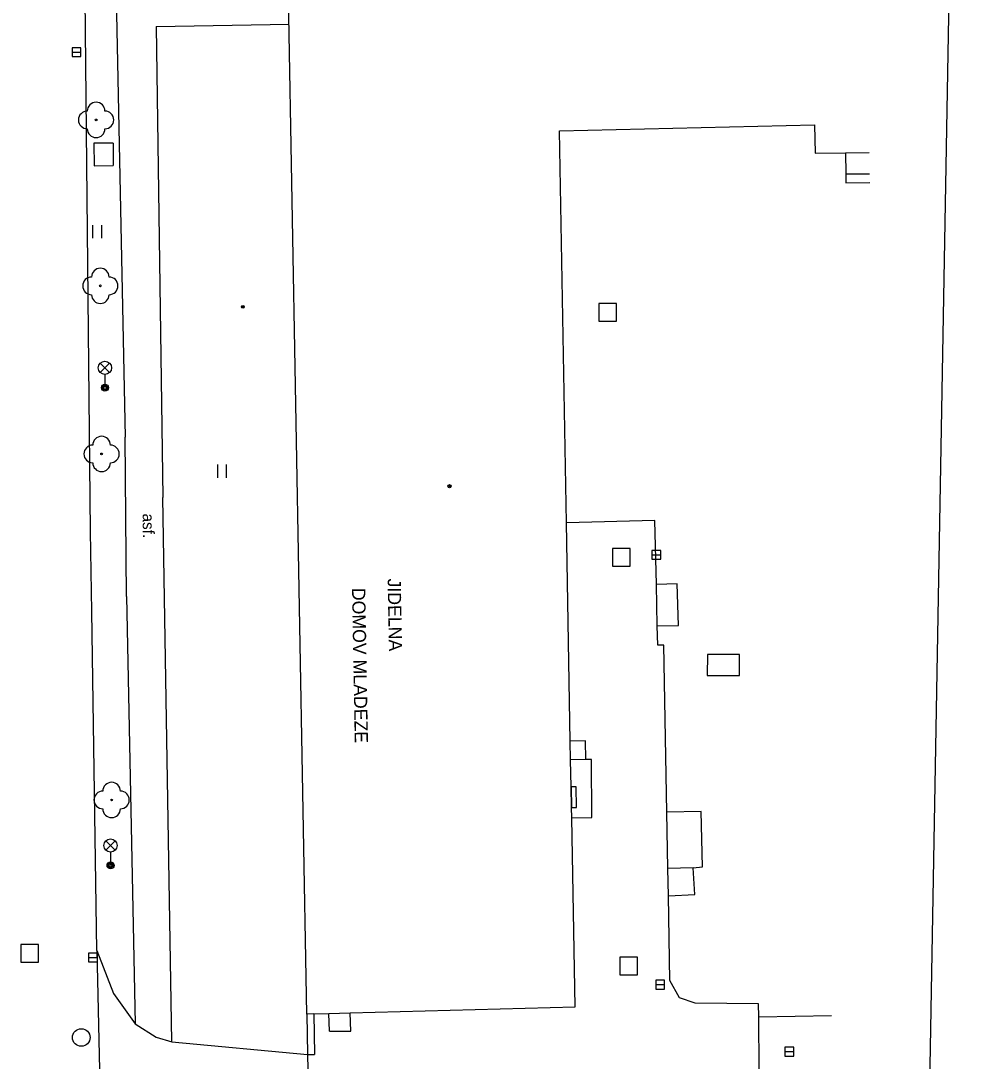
# Model space of a CAD drawing. Extents: x -641829 to -641525, y -1114855 to -1114359.
# Drawn here: x -641579.2 to -641525.3, y -1114496 to -1114437 of the extents above; entities that cross this region are included whole.
import ezdxf

# ---------------------------------------------------------------- set-up
doc = ezdxf.new("R2010")
doc.units = 0
for name, color, linetype in [('Vrstva 1', 7, 'Continuous'), ('Vrstva 10', 7, 'Continuous'), ('Vrstva 11', 7, 'Continuous'), ('Vrstva 20', 7, 'Continuous'), ('Vrstva 22', 7, 'Continuous'), ('Vrstva 24', 7, 'Continuous'), ('Vrstva 26', 7, 'Continuous'), ('Vrstva 27', 7, 'Continuous'), ('Vrstva 33', 7, 'Continuous'), ('Vrstva 36', 7, 'Continuous'), ('Vrstva 39', 7, 'Continuous'), ('Vrstva 40', 7, 'Continuous'), ('Vrstva 41', 7, 'Continuous'), ('Vrstva 5', 7, 'Continuous'), ('Vrstva 7', 7, 'Continuous'), ('Vrstva 8', 7, 'Continuous')]:
    doc.layers.add(name, color=color, linetype=linetype)

msp = doc.modelspace()

# ---------------------------------------------------------------- linework, layer by layer
at = {"layer": 'Vrstva 1'}
msp.add_line((-641533.66, -1114832.21), (-641525.3, -1114362.64), dxfattribs=at)
at = {"layer": 'Vrstva 10'}
for p, q in [((-641575.3, -1114465.98), (-641575.62, -1114434.15)), ((-641543.3, -1114465.35), (-641548.31, -1114465.48)), ((-641543.21, -1114468.98), (-641543.3, -1114465.35)), ((-641575.23, -1114470.51), (-641575.3, -1114465.98)), ((-641543.16, -1114471.33), (-641543.21, -1114468.98)), ((-641574.94, -1114489.73), (-641575.23, -1114470.51)), ((-641543.13, -1114472.43), (-641543.16, -1114471.33)), ((-641542.79, -1114472.42), (-641543.13, -1114472.43)), ((-641542.62, -1114481.89), (-641542.79, -1114472.42)), ((-641542.56, -1114485.08), (-641542.62, -1114481.89)), ((-641542.53, -1114486.64), (-641542.56, -1114485.08)), ((-641542.44, -1114491.44), (-641542.53, -1114486.64)), ((-641574.94, -1114489.73), (-641574.64, -1114503.41)), ((-641574.94, -1114489.73), (-641574, -1114492.18)), ((-641541.89, -1114492.42), (-641542.44, -1114491.44)), ((-641574, -1114492.18), (-641572.76, -1114493.9)), ((-641541.01, -1114492.72), (-641541.89, -1114492.42)), ((-641537.41, -1114492.76), (-641541.01, -1114492.72)), ((-641537.39, -1114493.5), (-641537.41, -1114492.76)), ((-641537.38, -1114496.49), (-641537.39, -1114493.5)), ((-641572.76, -1114493.9), (-641571.57, -1114494.65)), ((-641571.57, -1114494.65), (-641570.68, -1114494.91)), ((-641570.68, -1114494.91), (-641562.99, -1114495.64))]:
    msp.add_line(p, q, dxfattribs=at)
at = {"layer": 'Vrstva 11'}
for p, q in [((-641573.9, -1114433.06), (-641573.34, -1114460.63)), ((-641571.58, -1114437.35), (-641564.04, -1114437.21)), ((-641571.58, -1114437.35), (-641571.19, -1114464.05)), ((-641575.11, -1114443.96), (-641575.09, -1114445.24)), ((-641574.02, -1114443.96), (-641575.11, -1114443.96)), ((-641574.02, -1114443.96), (-641574.02, -1114445.22)), ((-641532.49, -1114444.5), (-641532.47, -1114445.7)), ((-641575.09, -1114445.24), (-641574.02, -1114445.22)), ((-641532.47, -1114445.7), (-641531.12, -1114445.69)), ((-641532.47, -1114445.7), (-641532.47, -1114446.2)), ((-641532.47, -1114446.2), (-641531.11, -1114446.19)), ((-641573.26, -1114469.66), (-641573.34, -1114460.63)), ((-641570.68, -1114494.91), (-641571.19, -1114464.05)), ((-641542.03, -1114468.95), (-641543.21, -1114468.98)), ((-641541.95, -1114471.3), (-641542.03, -1114468.95)), ((-641573.26, -1114469.66), (-641572.76, -1114493.9)), ((-641543.16, -1114471.33), (-641541.95, -1114471.3)), ((-641540.31, -1114472.95), (-641540.32, -1114474.14)), ((-641538.49, -1114472.96), (-641540.31, -1114472.95)), ((-641538.5, -1114474.15), (-641538.49, -1114472.96)), ((-641540.32, -1114474.14), (-641538.5, -1114474.15)), ((-641547.23, -1114477.85), (-641548.09, -1114477.87)), ((-641547.21, -1114478.91), (-641547.23, -1114477.85)), ((-641546.88, -1114478.9), (-641547.21, -1114478.91)), ((-641546.87, -1114482.19), (-641546.88, -1114478.9)), ((-641547.21, -1114478.91), (-641548.07, -1114478.92)), ((-641540.66, -1114481.85), (-641542.62, -1114481.89)), ((-641540.59, -1114484.99), (-641540.66, -1114481.85)), ((-641548.01, -1114482.21), (-641546.87, -1114482.19)), ((-641541.12, -1114485.05), (-641542.56, -1114485.08)), ((-641541.12, -1114485.05), (-641540.59, -1114484.99)), ((-641541.02, -1114486.56), (-641541.12, -1114485.05)), ((-641542.53, -1114486.64), (-641541.02, -1114486.56)), ((-641561.75, -1114494.31), (-641561.78, -1114493.31)), ((-641560.54, -1114494.31), (-641560.57, -1114493.27)), ((-641537.39, -1114493.5), (-641533.28, -1114493.43)), ((-641561.75, -1114494.31), (-641560.54, -1114494.31))]:
    msp.add_line(p, q, dxfattribs=at)
at = {"layer": 'Vrstva 20'}
for radius in [0.075, 0.0204]:
    msp.add_circle((-641566.66, -1114453.24), radius, dxfattribs=at)
at = {"layer": 'Vrstva 22'}
for centre in [(-641574.98, -1114442.64), (-641574.74, -1114452.05), (-641574.67, -1114461.58), (-641574.1, -1114481.2)]:
    msp.add_circle(centre, 0.05, dxfattribs=at)
for centre, start, end in [((-641574.98, -1114442.14), 0, 180), ((-641575.48, -1114442.64), 90, 270), ((-641574.48, -1114442.64), 270, 90), ((-641574.98, -1114443.14), 180, 0), ((-641574.74, -1114451.55), 0, 180), ((-641575.24, -1114452.05), 90, 270), ((-641574.24, -1114452.05), 270, 90), ((-641574.74, -1114452.55), 180, 0), ((-641574.67, -1114461.08), 0, 180), ((-641575.17, -1114461.58), 90, 270), ((-641574.17, -1114461.58), 270, 90), ((-641574.67, -1114462.08), 180, 0), ((-641574.1, -1114480.7), 0, 180), ((-641574.6, -1114481.2), 90, 270), ((-641573.6, -1114481.2), 270, 90), ((-641574.1, -1114481.7), 180, 0)]:
    msp.add_arc(centre, 0.5, start, end, dxfattribs=at)
at = {"layer": 'Vrstva 24'}
msp.add_lwpolyline([(-641547.74, -1114481.62), (-641547.76, -1114480.45), (-641548.04, -1114480.46), (-641548.02, -1114481.63), (-641547.74, -1114481.62)], dxfattribs=at)
at = {"layer": 'Vrstva 26'}
for points in [[(-641546.47, -1114454.05), (-641545.47, -1114454.05), (-641545.47, -1114453.05), (-641546.47, -1114453.05)], [(-641545.7, -1114467.94), (-641544.7, -1114467.94), (-641544.7, -1114466.94), (-641545.7, -1114466.94)], [(-641578.25, -1114489.39), (-641579.25, -1114489.39), (-641579.25, -1114490.39), (-641578.25, -1114490.39)], [(-641545.28, -1114491.11), (-641544.28, -1114491.11), (-641544.28, -1114490.11), (-641545.28, -1114490.11)]]:
    msp.add_lwpolyline(points, close=True, dxfattribs=at)
at = {"layer": 'Vrstva 27'}
for p, q in [((-641576.34, -1114438.8), (-641575.84, -1114438.8)), ((-641543.46, -1114467.3), (-641542.96, -1114467.3)), ((-641575.41, -1114490.13), (-641574.91, -1114490.13)), ((-641543.24, -1114491.67), (-641542.74, -1114491.67)), ((-641535.92, -1114495.47), (-641535.42, -1114495.47))]:
    msp.add_line(p, q, dxfattribs=at)
for points in [[(-641576.34, -1114439.05), (-641575.84, -1114439.05), (-641575.84, -1114438.55), (-641576.34, -1114438.55)], [(-641543.46, -1114467.55), (-641542.96, -1114467.55), (-641542.96, -1114467.05), (-641543.46, -1114467.05)], [(-641575.41, -1114490.38), (-641574.91, -1114490.38), (-641574.91, -1114489.88), (-641575.41, -1114489.88)], [(-641543.24, -1114491.92), (-641542.74, -1114491.92), (-641542.74, -1114491.42), (-641543.24, -1114491.42)], [(-641535.92, -1114495.72), (-641535.42, -1114495.72), (-641535.42, -1114495.22), (-641535.92, -1114495.22)]]:
    msp.add_lwpolyline(points, close=True, dxfattribs=at)
msp.add_circle((-641575.82, -1114494.67), 0.5, dxfattribs=at)
at = {"layer": 'Vrstva 33'}
for p, q in [((-641574.745, -1114456.96), (-641574.215, -1114456.43)), ((-641574.745, -1114456.43), (-641574.215, -1114456.96)), ((-641574.48, -1114457.07), (-641574.48, -1114457.82)), ((-641574.425, -1114484.05), (-641573.895, -1114483.52)), ((-641574.425, -1114483.52), (-641573.895, -1114484.05)), ((-641574.16, -1114484.16), (-641574.16, -1114484.91))]:
    msp.add_line(p, q, dxfattribs=at)
for centre, radius in [((-641574.48, -1114456.695), 0.375), ((-641574.48, -1114457.82), 0.2), ((-641574.48, -1114457.82), 0.145), ((-641574.48, -1114457.82), 0.0876), ((-641574.16, -1114483.785), 0.375), ((-641574.16, -1114484.91), 0.2), ((-641574.16, -1114484.91), 0.145), ((-641574.16, -1114484.91), 0.0876)]:
    msp.add_circle(centre, radius, dxfattribs=at)
at = {"layer": 'Vrstva 36'}
for p, q in [((-641575.164, -1114449.352), (-641575.164, -1114448.604)), ((-641574.664, -1114449.352), (-641574.664, -1114448.604)), ((-641568.084, -1114462.932), (-641568.084, -1114462.184)), ((-641567.584, -1114462.932), (-641567.584, -1114462.184))]:
    msp.add_line(p, q, dxfattribs=at)
at = {"layer": 'Vrstva 39'}
for radius in [0.09, 0.0398]:
    msp.add_circle((-641554.94, -1114463.41), radius, dxfattribs=at)
at = {"layer": 'Vrstva 5'}
for p, q in [((-641563.03, -1114493.34), (-641564.11, -1114433.5)), ((-641548.71, -1114443.25), (-641534.25, -1114442.92)), ((-641534.25, -1114442.92), (-641534.21, -1114444.52)), ((-641548.31, -1114465.48), (-641548.71, -1114443.25)), ((-641534.21, -1114444.52), (-641532.49, -1114444.5)), ((-641532.49, -1114444.5), (-641531.15, -1114444.48)), ((-641548.09, -1114477.87), (-641548.31, -1114465.48)), ((-641548.07, -1114478.92), (-641548.09, -1114477.87)), ((-641548.04, -1114480.46), (-641548.07, -1114478.92)), ((-641548.01, -1114482.21), (-641548.02, -1114481.63)), ((-641547.82, -1114492.93), (-641548.01, -1114482.21)), ((-641560.57, -1114493.27), (-641547.82, -1114492.93)), ((-641562.63, -1114493.33), (-641563.03, -1114493.34)), ((-641562.63, -1114493.33), (-641561.78, -1114493.31)), ((-641561.78, -1114493.31), (-641560.57, -1114493.27))]:
    msp.add_line(p, q, dxfattribs=at)
msp.add_lwpolyline([(-641548.02, -1114481.63), (-641548.04, -1114480.46)], dxfattribs=at)
at = {"layer": 'Vrstva 7'}
for p, q in [((-641563.03, -1114493.34), (-641562.99, -1114495.64)), ((-641562.63, -1114493.33), (-641562.59, -1114495.63)), ((-641562.99, -1114495.64), (-641562.59, -1114495.63))]:
    msp.add_line(p, q, dxfattribs=at)
at = {"layer": 'Vrstva 8'}
msp.add_line((-641562.99, -1114495.64), (-641562.93, -1114499.44), dxfattribs=at)

# ---------------------------------------------------------------- texts
at = {"layer": 'Vrstva 40'}
msp.add_text('asf.', height=0.65, rotation=270.50759, dxfattribs=at).set_placement((-641572.34, -1114464.96))
at = {"layer": 'Vrstva 41'}
for s, p in [('JIDELNA', (-641558.45, -1114468.65)), ('DOMOV MLADEZE', (-641560.47, -1114469.18))]:
    msp.add_text(s, height=0.75, rotation=271.03397, dxfattribs=at).set_placement(p)

doc.saveas('drawing.dxf')
